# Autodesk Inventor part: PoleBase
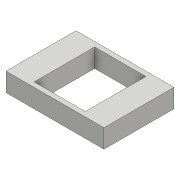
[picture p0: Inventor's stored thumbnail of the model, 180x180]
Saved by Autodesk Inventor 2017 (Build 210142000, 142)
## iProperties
Part Number: PoleBase
Material: 一般
Document SubType Name: Modeling
Designer: kyushu-hep
Density: 1 g/cm^3
Appearance: 既定
Author: kyushu-hep
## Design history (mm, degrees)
sketch "スケッチ1"
  geometry: L1 (-9.744, 67.452)-(95.256, 67.452); L2 (95.256, 67.452)-(95.256, -7.548); L3 (95.256, -7.548)-(-9.744, -7.548); L4 (-9.744, -7.548)-(-9.744, 67.452); 1 further point
  constraints: 8 end point, 2 parallel, 1 horizontal, 1 perpendicular
  dimensions: "d0" = 105 distance of L2.end L3.end; "d1" = 75 distance of L3.end L1.start
extrude "押し出し1" new body sketch "スケッチ1" distance "d2" = 20; taper "d3" = 0 deg
sketch "スケッチ2"
  geometry: L1 (15.256, 62.452)-(70.256, 62.452); L2 (70.256, 62.452)-(70.256, -2.548); L3 (70.256, -2.548)-(15.256, -2.548); L4 (15.256, -2.548)-(15.256, 62.452); L5 (-9.744, -7.548)-(95.256, -7.548) reference; L6 (-9.744, 67.452)-(-9.744, -7.548) reference; 1 further point
  constraints: 8 end point, 2 parallel, 1 horizontal, 1 perpendicular
  dimensions: "d4" = 55 distance of L2.end L3.end; "d5" = 65 distance of L3.end L1.start; "d6" = 5 distance between parallel lines of L5 L3; "d7" = 25 distance between parallel lines of L6 L4
extrude "押し出し2" cut sketch "スケッチ2" distance "d8" = 20; taper "d9" = 0 deg
node "ソリッド1"
